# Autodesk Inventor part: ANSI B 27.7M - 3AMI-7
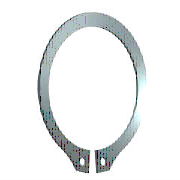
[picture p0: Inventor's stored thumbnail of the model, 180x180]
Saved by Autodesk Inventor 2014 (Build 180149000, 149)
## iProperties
IsCustomPart: 0
Created: 2008-02
Part Number: ANSI B 27.7M - 3AMI-7
Material: Steel, Mild
Description: Metric Snap Ring
Document SubType Name: Modeling
Standard: ANSI B 27.7M
Designer: PN
Standards Organization: ANSI
Language: en-US
Size Designation: 3AMI-7
Categories: <MemberInstance><Categories><Category DisplayName="Shaft Parts" InternalName="7f7aeb1f-a693-4053-b835-cee3144e0d98" Mnemonic="SHFT"><Category DisplayName="Circl
Density: 7.86 g/cm^3
Mass: 0.16205 g
Surface Area: 1.07811 cm^2
Volume: 0.0206171 cm^3
Appearance: 179,145,89
Author: PN
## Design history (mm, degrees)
body "Solid1"
sketch "Sketch2"
  geometry: L1 (-0.517, -6.359)-(-2.677, -6.359); L2 (-0.517, -3.259)-(-0.517, -6.359); L3 (0, -9.315)-(0, 7.036) reference; L4 (0.517, -6.359)-(2.677, -6.359); L5 (0.517, -3.259)-(0.517, -6.359); A1 r 3.3 centre (0, 0) between (0.517, -3.259) and (-0.517, -3.259); A2 r 4.233 centre (0, 0.467) between (3.873, -1.243) and (-3.873, -1.243); A3 r 14.206 centre (-16.869, -6.979) between (-2.677, -6.359) and (-3.873, -1.243); A4 r 14.206 centre (16.869, -6.979) between (3.873, -1.243) and (2.677, -6.359); 1 further point
  constraints: 9 point on circle, 9 symmetric about line, 8 end point, 4 centre point, 1 coincident, 1 horizontal, 1 point on line, 1 tangent, 1 vertical, 3 other
  dimensions: "d15" = 0.46667 distance of A2.centre A1.centre (= 0.333333 x b); "d28" = 6.6 diameter of A1 (= g1); "d32" = 1.4 dimension on A2 A1 (= b); "d34" = 3.1 distance of L2.start L1.start (= ParA); "d35" = 1.03333 distance between parallel lines of L5 L2 (= 0.333333 x ParA); "d48" = 2.16 distance of L1.start L1.end (= 1.8 x Diam5); "d49" = 0.62 distance from line of A3.centre L1 (= 0.2 x ParA)
extrude "Extrusion1" new body sketch "Sketch2" distance "d16" = 0.6 (= tt); taper "d17" = 0 deg
sketch "Sketch3"
  geometry: L1 (-0.517, -6.359)-(-2.677, -6.359) reference; L2 (0.517, -6.359)-(0.517, -3.259) reference; L3 (2.677, -6.359)-(0.517, -6.359) reference; L4 (0, -6.979)-(0, -2.639) reference; C1 r 0.6 at (-1.657, -4.809); C2 r 0.6 at (1.657, -4.809)
  constraints: 2 centre point, 1 symmetric about line, 1 other
  dimensions: "d36" = 1.2 diameter of C1 (= Diam5); "d37" = 1.55 distance from line of L1 C1.centre (= 0.5 x ParA); "d47" = 3.31333 diameter of C1.centre L4 (= 0.333333 x ParA + 1.9 x Diam5)
extrude "Extrusion2" cut sketch "Sketch3" stored distance "d26" = 0.13; taper "d27" = 0 deg
other parameters: "g1" = 6.6 [user parameter; used in 1 equation term], "ParA" = 3.1 [user parameter; used in 5 equation terms], "b" = 1.4 [user parameter; used in 2 equation terms], "tt" = 0.6 [user parameter; used in 1 equation term], "Diam5" = 1.2 [user parameter; used in 3 equation terms], "d0" = 0 (derived), "d2" = 1.9 (derived), "d4" = 0.55 (derived), "d6" = 2.2 (derived), "d8" = 1.65 (derived), "d10" = 3.3 (derived), "d12" = 0.44 (derived), "d14" = 0.3 (derived), "d18" = 1.1 (derived), "d20" = 0.99 (derived), "d22" = 0.99 (derived), "d24" = 1 (derived), "d51" = 0, "d52" = 0, "d53" = 0, "d54" = 0, "TEMPLATE" = 12.345 [user parameter]
